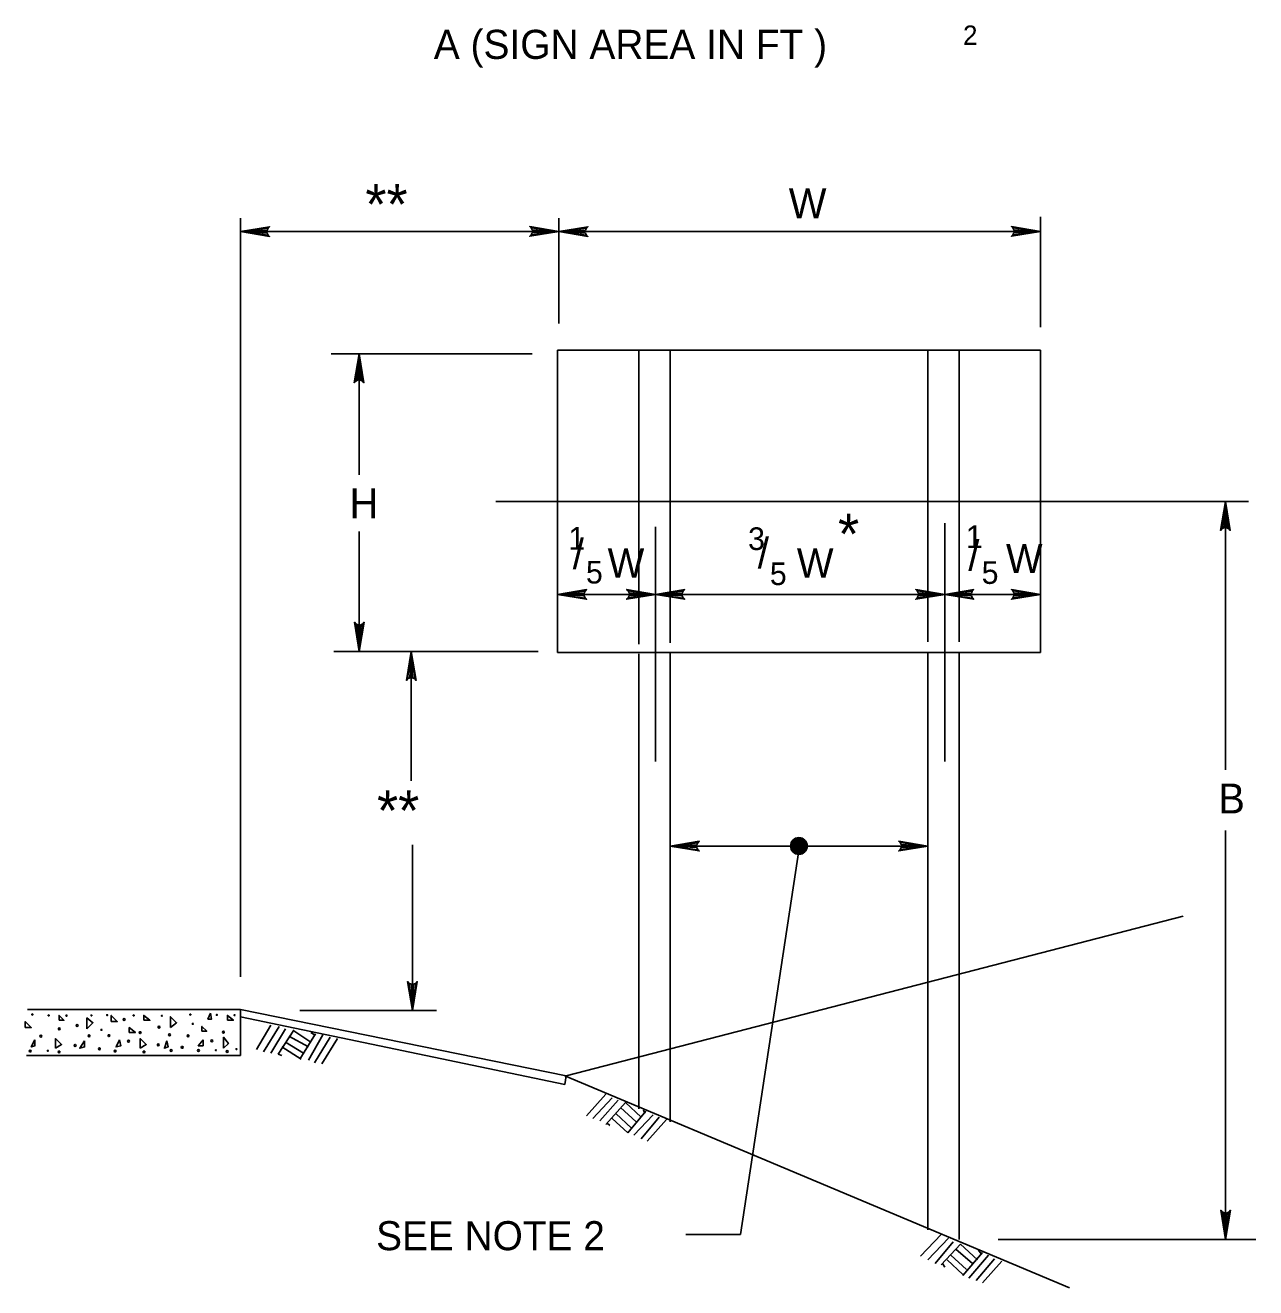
# Model space of a CAD drawing. Extents: x 644358 to 648627, y 294594 to 295782.
# Drawn here: x 645593.3 to 645720.4, y 295496.9 to 295627.3 of the extents above; entities that cross this region are included whole.
import ezdxf

# ---------------------------------------------------------------- set-up
doc = ezdxf.new("R2010")
doc.units = 0
for name, color, linetype in [('1', 7, 'Continuous'), ('2', 7, 'Continuous'), ('3', 7, 'Continuous'), ('4', 7, 'Continuous')]:
    doc.layers.add(name, color=color, linetype=linetype)

# ---------------------------------------------------------------- blocks, each defined once
blk = doc.blocks.new('RARROW')
at = {"layer": '3'}
blk.add_lwpolyline([(-2.2695, 0.285), (-2.184875, 0.12075), (0, 0), (-2.2695, 0.285), (-2.38575, 0.384625), (0, 0), (-2.183125, -0.108), (-2.262875, -0.2705), (0, 0), (-2.38575, -0.379125), (-2.262875, -0.2705)], dxfattribs=at)

msp = doc.modelspace()

# ---------------------------------------------------------------- linework, layer by layer
at = {"layer": '1'}
for p, q in [((645618.69, 295524.04), (645617.19, 295521.54)), ((645619.56, 295523.91), (645617.94, 295521.29)), ((645620.19, 295523.66), (645618.69, 295521.16)), ((645621.06, 295523.54), (645619.44, 295521.04)), ((645622.81, 295522.29), (645620.94, 295523.54)), ((645622.06, 295521.16), (645620.19, 295522.29)), ((645622.56, 295521.79), (645620.56, 295522.91)), ((645623.31, 295523.16), (645621.69, 295520.54)), ((645624.06, 295523.04), (645622.56, 295520.41)), ((645623.19, 295523.04), (645622.81, 295523.29)), ((645624.81, 295522.79), (645623.19, 295520.16)), ((645625.56, 295522.66), (645623.94, 295520.04)), ((645619.81, 295520.91), (645619.44, 295521.04)), ((645621.81, 295520.54), (645619.81, 295521.79)), ((645653.31, 295516.91), (645651.31, 295514.66)), ((645653.94, 295516.54), (645651.94, 295514.41)), ((645654.56, 295516.29), (645652.69, 295514.16)), ((645655.31, 295516.04), (645653.31, 295513.79)), ((645656.94, 295514.54), (645655.31, 295516.04)), ((645655.56, 295512.91), (645653.94, 295514.41)), ((645655.94, 295513.41), (645654.31, 295514.91)), ((645656.44, 295514.04), (645654.81, 295515.54)), ((645657.44, 295515.16), (645655.56, 295512.91)), ((645658.19, 295514.79), (645656.19, 295512.66)), ((645658.81, 295514.54), (645656.94, 295512.29)), ((645657.31, 295514.91), (645657.19, 295515.29)), ((645653.69, 295513.66), (645653.44, 295513.91)), ((645659.56, 295514.29), (645657.56, 295512.04)), ((645687.94, 295502.41), (645685.81, 295500.16)), ((645688.69, 295502.04), (645686.56, 295499.79)), ((645689.19, 295501.66), (645687.31, 295499.41)), ((645689.94, 295501.41), (645687.94, 295499.29)), ((645691.69, 295499.79), (645689.94, 295501.41)), ((645690.56, 295498.79), (645688.94, 295500.29)), ((645691.19, 295499.41), (645689.44, 295500.91)), ((645692.19, 295500.54), (645690.19, 295498.16)), ((645692.81, 295500.29), (645690.81, 295497.91)), ((645692.06, 295500.41), (645691.81, 295500.79)), ((645688.31, 295499.04), (645688.06, 295499.41)), ((645690.19, 295498.29), (645688.56, 295499.79)), ((645693.44, 295499.91), (645691.56, 295497.66)), ((645694.19, 295499.66), (645692.19, 295497.41))]:
    msp.add_line(p, q, dxfattribs=at)
for points in [[(645596.81, 295524.54), (645596.81, 295525.04), (645597.31, 295524.54)], [(645599.69, 295523.66), (645599.69, 295524.79), (645600.31, 295524.29)], [(645602.19, 295524.41), (645602.19, 295525.04), (645602.81, 295524.41)], [(645605.56, 295524.54), (645605.56, 295525.04), (645606.19, 295524.54)], [(645608.31, 295523.79), (645608.31, 295524.91), (645608.94, 295524.29)], [(645612.44, 295525.29), (645612.56, 295524.66), (645612.19, 295524.66)], [(645614.19, 295524.54), (645614.19, 295525.04), (645614.81, 295524.54)], [(645593.31, 295523.79), (645593.31, 295524.41), (645593.94, 295523.79)], [(645604.06, 295523.29), (645604.06, 295523.79), (645604.69, 295523.29)], [(645611.56, 295523.41), (645611.56, 295523.91), (645612.06, 295523.41)], [(645594.31, 295522.54), (645594.31, 295521.91), (645593.94, 295521.79)], [(645596.44, 295521.66), (645596.44, 295522.66), (645597.06, 295522.04)], [(645599.44, 295522.41), (645599.44, 295521.79), (645598.94, 295521.66)], [(645603.06, 295522.54), (645603.19, 295521.91), (645602.69, 295521.79)], [(645605.19, 295521.66), (645605.19, 295522.66), (645605.81, 295522.04)], [(645607.94, 295522.41), (645608.06, 295521.79), (645607.69, 295521.66)], [(645611.69, 295522.54), (645611.69, 295521.91), (645611.19, 295521.91)], [(645613.81, 295521.66), (645613.81, 295522.79), (645614.31, 295522.16)]]:
    msp.add_lwpolyline(points, close=True, dxfattribs=at)
for centre, radius in [((645594.04, 295525.14), 0.056), ((645595.73, 295525.05), 0.056), ((645597.57, 295525.02), 0.056), ((645600.15, 295525.05), 0.056), ((645601.77, 295525.08), 0.056), ((645604.51, 295525.05), 0.056), ((645607.43, 295525.01), 0.056), ((645610.37, 295525.13), 0.056), ((645613.1, 295525.1), 0.056), ((645614.94, 295525.07), 0.056), ((645596.83, 295523.66), 0.0979), ((645598.67, 295524.01), 0.0979), ((645601.19, 295523.56), 0.056), ((645603.52, 295524.62), 0.0979), ((645607.13, 295523.84), 0.0979), ((645610.63, 295524.18), 0.056), ((645594.93, 295522.91), 0.0979), ((645599.9, 295522.93), 0.0979), ((645601.96, 295522.96), 0.0979), ((645603.98, 295522.38), 0.0979), ((645605.18, 295523.27), 0.0979), ((645608.22, 295523.05), 0.0979), ((645610.13, 295522.94), 0.0979), ((645612.58, 295522.43), 0.0979), ((645613.78, 295523.32), 0.0979), ((645593.83, 295521.37), 0.0979), ((645595.64, 295521.4), 0.056), ((645596.8, 295521.27), 0.0979), ((645598.46, 295521.95), 0.0979), ((645600.97, 295521.59), 0.0979), ((645602.6, 295521.37), 0.0979), ((645605.58, 295521.27), 0.0979), ((645607.06, 295522), 0.0979), ((645608.38, 295521.42), 0.0979), ((645609.53, 295521.75), 0.0979), ((645611.2, 295521.42), 0.0979), ((645613.01, 295521.45), 0.056), ((645614.18, 295521.32), 0.0979), ((645615.13, 295521.57), 0.056)]:
    msp.add_circle(centre, radius, dxfattribs=at)
at = {"layer": '2'}
for p, q in [((645648.31, 295593.79), (645648.31, 295562.54)), ((645698.19, 295593.79), (645648.31, 295593.79)), ((645656.69, 295593.79), (645656.69, 295563.41)), ((645659.94, 295593.79), (645659.94, 295563.54)), ((645686.56, 295593.79), (645686.56, 295563.66)), ((645689.81, 295593.79), (645689.81, 295563.66)), ((645698.19, 295562.54), (645698.19, 295593.79)), ((645688.31, 295575.91), (645688.31, 295551.29)), ((645658.44, 295575.54), (645658.44, 295551.29)), ((645648.31, 295562.54), (645698.19, 295562.54)), ((645648.31, 295562.54), (645648.31, 295562.54)), ((645656.69, 295562.41), (645656.69, 295515.41)), ((645659.94, 295562.54), (645659.94, 295514.04)), ((645686.56, 295562.54), (645686.56, 295502.91)), ((645689.81, 295562.54), (645689.81, 295501.91)), ((645649.19, 295518.79), (645712.94, 295535.29)), ((645615.56, 295525.66), (645593.56, 295525.66)), ((645615.56, 295525.66), (645649.19, 295518.79)), ((645615.56, 295525.66), (645615.56, 295520.91)), ((645615.56, 295524.91), (645649.06, 295517.91)), ((645615.56, 295520.91), (645593.44, 295520.91)), ((645649.06, 295518.79), (645701.19, 295496.91)), ((645649.19, 295518.79), (645649.06, 295517.91))]:
    msp.add_line(p, q, dxfattribs=at)
at = {"layer": '4'}
for p, q in [((645615.56, 295607.41), (645615.56, 295529.04)), ((645648.44, 295607.41), (645648.44, 295596.54)), ((645698.19, 295607.54), (645698.19, 295596.16)), ((645648.44, 295606.04), (645615.56, 295606.04)), ((645698.06, 295606.04), (645648.44, 295606.04)), ((645645.69, 295593.41), (645624.93, 295593.41)), ((645627.81, 295593.41), (645627.81, 295580.91)), ((645641.94, 295578.16), (645719.69, 295578.16)), ((645717.31, 295578.16), (645717.31, 295550.41)), ((645627.81, 295575.04), (645627.81, 295562.66)), ((645648.44, 295568.54), (645648.31, 295568.54)), ((645658.31, 295568.54), (645648.44, 295568.54)), ((645688.31, 295568.54), (645658.31, 295568.54)), ((645698.06, 295568.54), (645688.31, 295568.54)), ((645698.19, 295568.54), (645698.06, 295568.54)), ((645646.31, 295562.66), (645625.18, 295562.66)), ((645633.19, 295562.66), (645633.19, 295549.29)), ((645717.31, 295544.16), (645717.31, 295501.91)), ((645633.31, 295542.66), (645633.31, 295525.54)), ((645686.56, 295542.54), (645659.94, 295542.54)), ((645673.31, 295542.54), (645667.19, 295502.41)), ((645635.81, 295525.54), (645621.69, 295525.54)), ((645667.19, 295502.41), (645661.56, 295502.41)), ((645720.44, 295501.91), (645693.81, 295501.91))]:
    msp.add_line(p, q, dxfattribs=at)
for radius in [0.867, 0.806, 0.744, 0.682, 0.621, 0.559, 0.498, 0.436, 0.374, 0.313, 0.251, 0.19, 0.128, 0.0665]:
    msp.add_circle((645673.24, 295542.55), radius, dxfattribs=at)

# ---------------------------------------------------------------- block references
at = {"layer": '2', "xscale": 1.2574347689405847, "yscale": 1.3092961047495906}
for p, rotation in [((645615.56, 295606.04), 180), ((645648.44, 295606.04), 180), ((645627.81, 295593.41), 89.99999999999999), ((645717.31, 295578.16), 89.99999999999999), ((645648.31, 295568.54), 180), ((645658.44, 295568.54), 180), ((645688.31, 295568.54), 180), ((645627.81, 295562.66), -90.00000000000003), ((645633.19, 295562.66), 89.99999999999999), ((645659.94, 295542.54), 180), ((645633.31, 295525.54), -90.00000000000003), ((645717.31, 295501.91), -90.00000000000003)]:
    msp.add_blockref('RARROW', p, dxfattribs=dict(at, rotation=rotation))
for p in [(645648.44, 295606.04), (645698.19, 295606.04), (645658.44, 295568.54), (645688.31, 295568.54), (645698.19, 295568.54), (645686.56, 295542.54)]:
    msp.add_blockref('RARROW', p, dxfattribs=at)

# ---------------------------------------------------------------- texts
at = {"layer": '4'}
msp.add_text('A (SIGN AREA IN FT )', height=3.005, rotation=360, dxfattribs=at).set_placement((645635.52, 295623.87))
for s, height, p in [('2', 2, (645690.2, 295625.32)), ('**', 4.2, (645628.45, 295606.75)), ('W', 3.09, (645672.19, 295607.41)), ('H', 3.09, (645626.81, 295576.41)), ('*', 4.2, (645677.28, 295572.69)), ('1', 2.34, (645690.49, 295573.34)), ('1', 2.34, (645649.42, 295573.17)), ('/', 3.11, (645649.87, 295571.17)), ('3', 2.34, (645667.99, 295573.13)), ('/', 3.11, (645668.99, 295571.26)), ('W', 3, (645653.48, 295570.29)), ('W', 3, (645673.03, 295570.29)), ('/', 3.11, (645690.74, 295571.01)), ('W', 3, (645694.63, 295570.76)), ('5', 2.34, (645651.24, 295569.67)), ('5', 2.34, (645670.24, 295569.51)), ('5', 2.34, (645692.12, 295569.63)), ('**', 4.2, (645629.65, 295544.11)), ('B', 3.09, (645716.56, 295545.91)), ('SEE NOTE 2', 3, (645629.56, 295500.79))]:
    msp.add_text(s, height=height, dxfattribs=at).set_placement(p)

doc.saveas('drawing.dxf')
